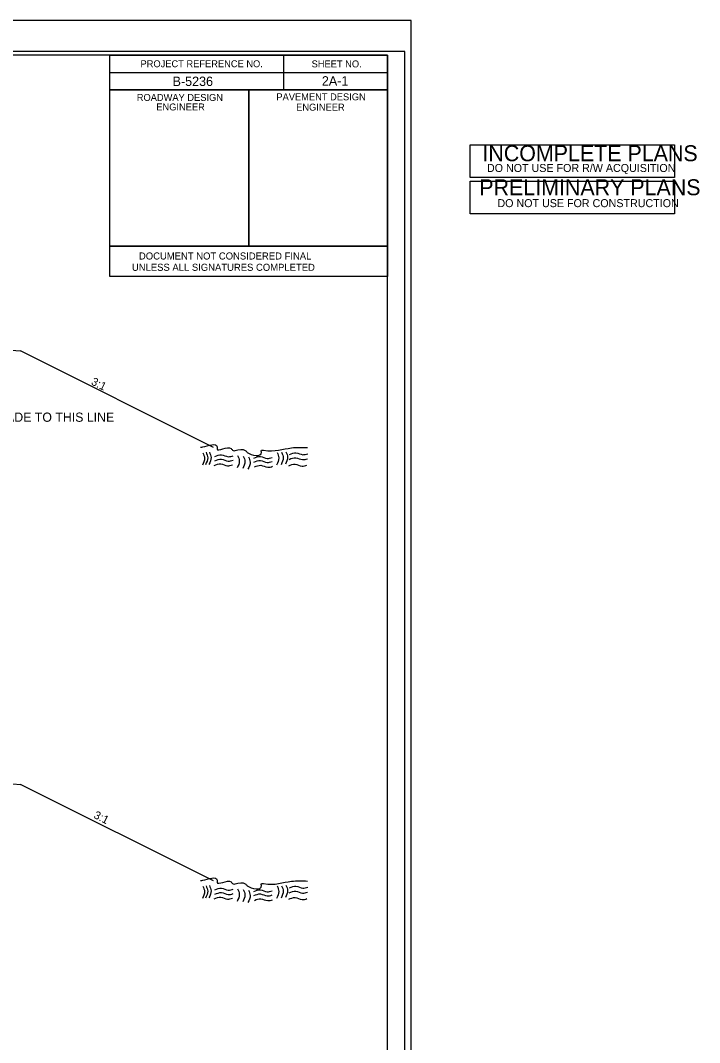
# Model space of a CAD drawing. Extents: x 1733676 to 1734289, y 540979 to 541226.
# Drawn here: x 1734236.1 to 1734288.9, y 541146.4 to 541225.9 of the extents above; entities that cross this region are included whole.
import ezdxf

# ---------------------------------------------------------------- set-up
doc = ezdxf.new("R2010")
doc.units = 0
for name, color, linetype in [('Old_Level_2', 7, 'Continuous'), ('Sheet Cutting Line CELL', 7, 'Continuous'), ('Sheet Data Field CELL', 7, 'Continuous'), ('Sheet Plot Border Inside CELL', 7, 'Continuous'), ('Sheet Plot Border Outside CELL', 7, 'Continuous'), ('Sheet Sticker Exception Certification CELL', 7, 'Continuous'), ('Sheet Sticker Incomplete CELL', 7, 'Continuous'), ('Sheet Sticker Preliminary CELL', 7, 'Continuous'), ('Sheet Typical CELL', 7, 'Continuous'), ('Typical Pavement Slope CELL', 7, 'Continuous'), ('Typical Slope Point Local CELL', 7, 'Continuous'), ('Typical Text General CELL', 7, 'Continuous')]:
    doc.layers.add(name, color=color, linetype=linetype)

msp = doc.modelspace()

# ---------------------------------------------------------------- linework, layer by layer
at = {"layer": 'Old_Level_2'}
for points in [[(1734250.132, 541192.695), (1734250.318, 541192.717), (1734251.415, 541192.73), (1734251.417, 541192.573), (1734252.513, 541192.586), (1734252.671, 541192.431), (1734252.828, 541192.433), (1734253.611, 541192.442), (1734253.77, 541192.287), (1734254.866, 541192.3), (1734254.864, 541192.456), (1734255.021, 541192.458), (1734257.212, 541192.64), (1734258.46, 541192.655)], [(1734250.315, 541192.256), (1734250.443, 541191.836), (1734250.274, 541191.29)], [(1734250.56, 541192.294), (1734250.688, 541191.874), (1734250.519, 541191.328)], [(1734250.823, 541192.314), (1734250.951, 541191.895), (1734250.782, 541191.349)], [(1734251.257, 541191.977), (1734251.764, 541192.106), (1734252.292, 541191.954), (1734252.677, 541192.029)], [(1734253.019, 541192.042), (1734253.147, 541191.622), (1734252.978, 541191.076)], [(1734253.459, 541191.994), (1734253.586, 541191.574), (1734253.417, 541191.028)], [(1734254.276, 541191.837), (1734254.784, 541191.965), (1734255.312, 541191.814), (1734255.697, 541191.888)], [(1734256.087, 541192.27), (1734256.215, 541191.851), (1734256.046, 541191.305)], [(1734256.438, 541192.292), (1734256.565, 541191.872), (1734256.396, 541191.326)], [(1734256.771, 541192.331), (1734256.898, 541191.911), (1734256.729, 541191.365)], [(1734257.045, 541192.132), (1734257.552, 541192.261), (1734258.08, 541192.109), (1734258.466, 541192.184)], [(1734251.195, 541191.275), (1734251.702, 541191.403), (1734252.23, 541191.252), (1734252.615, 541191.326)], [(1734251.243, 541191.626), (1734251.751, 541191.755), (1734252.279, 541191.603), (1734252.664, 541191.678)], [(1734253.863, 541191.946), (1734253.99, 541191.527), (1734253.821, 541190.981)], [(1734254.28, 541191.521), (1734254.787, 541191.65), (1734255.315, 541191.498), (1734255.7, 541191.573)], [(1734254.319, 541191.153), (1734254.827, 541191.282), (1734255.355, 541191.13), (1734255.74, 541191.204)], [(1734256.985, 541191.237), (1734257.493, 541191.365), (1734258.021, 541191.213), (1734258.406, 541191.288)], [(1734257.032, 541191.746), (1734257.539, 541191.874), (1734258.067, 541191.723), (1734258.452, 541191.797)], [(1734250.132, 541158.995), (1734250.318, 541159.018), (1734251.415, 541159.03), (1734251.417, 541158.874), (1734252.513, 541158.887), (1734252.671, 541158.732), (1734252.828, 541158.734), (1734253.611, 541158.743), (1734253.77, 541158.588), (1734254.866, 541158.6), (1734254.864, 541158.757), (1734255.021, 541158.759), (1734257.212, 541158.941), (1734258.46, 541158.955)], [(1734250.56, 541158.594), (1734250.688, 541158.175), (1734250.519, 541157.629)], [(1734250.823, 541158.615), (1734250.951, 541158.195), (1734250.782, 541157.649)], [(1734256.771, 541158.631), (1734256.898, 541158.212), (1734256.729, 541157.666)], [(1734250.315, 541158.557), (1734250.443, 541158.137), (1734250.274, 541157.591)], [(1734251.243, 541157.927), (1734251.751, 541158.055), (1734252.279, 541157.904), (1734252.664, 541157.978)], [(1734251.257, 541158.278), (1734251.764, 541158.407), (1734252.292, 541158.255), (1734252.677, 541158.329)], [(1734253.019, 541158.342), (1734253.147, 541157.923), (1734252.978, 541157.377)], [(1734253.459, 541158.295), (1734253.586, 541157.875), (1734253.417, 541157.329)], [(1734253.863, 541158.247), (1734253.99, 541157.827), (1734253.821, 541157.281)], [(1734254.276, 541158.137), (1734254.784, 541158.266), (1734255.312, 541158.114), (1734255.697, 541158.189)], [(1734254.28, 541157.822), (1734254.787, 541157.95), (1734255.315, 541157.798), (1734255.7, 541157.873)], [(1734256.087, 541158.571), (1734256.215, 541158.151), (1734256.046, 541157.605)], [(1734256.438, 541158.592), (1734256.565, 541158.173), (1734256.396, 541157.627)], [(1734257.032, 541158.046), (1734257.539, 541158.175), (1734258.067, 541158.023), (1734258.452, 541158.098)], [(1734257.045, 541158.433), (1734257.552, 541158.561), (1734258.08, 541158.41), (1734258.466, 541158.484)], [(1734251.195, 541157.575), (1734251.702, 541157.704), (1734252.23, 541157.552), (1734252.615, 541157.627)], [(1734254.319, 541157.454), (1734254.827, 541157.582), (1734255.355, 541157.431), (1734255.74, 541157.505)], [(1734256.985, 541157.537), (1734257.493, 541157.666), (1734258.021, 541157.514), (1734258.406, 541157.589)]]:
    msp.add_spline(points, degree=3, dxfattribs=at)
at = {"layer": 'Sheet Cutting Line CELL'}
msp.add_line((1734266.513, 541225.875), (1734084.641, 541225.875), dxfattribs=at)
at = {"layer": 'Sheet Plot Border Inside CELL'}
msp.add_lwpolyline([(1734266.027, 541223.451), (1734086.045, 541223.451), (1734086.045, 541109.5), (1734266.027, 541109.5)], close=True, dxfattribs=at)
at = {"layer": 'Sheet Plot Border Outside CELL'}
msp.add_lwpolyline([(1734266.513, 541225.875), (1734084.641, 541225.875), (1734084.641, 541107.075), (1734266.513, 541107.075)], close=True, dxfattribs=at)
at = {"layer": 'Sheet Sticker Exception Certification CELL'}
for p, q in [((1734243.071, 541205.97), (1734243.071, 541208.32)), ((1734243.071, 541208.32), (1734264.677, 541208.32)), ((1734264.677, 541208.319), (1734264.677, 541205.969)), ((1734264.677, 541205.97), (1734243.071, 541205.97))]:
    msp.add_line(p, q, dxfattribs=at)
at = {"layer": 'Sheet Sticker Incomplete CELL'}
msp.add_lwpolyline([(1734271.092, 541213.664), (1734271.092, 541216.202), (1734286.968, 541216.202), (1734286.968, 541213.664)], close=True, dxfattribs=at)
at = {"layer": 'Sheet Sticker Preliminary CELL'}
msp.add_lwpolyline([(1734271.092, 541210.844), (1734271.092, 541213.382), (1734286.968, 541213.382), (1734286.968, 541210.844)], close=True, dxfattribs=at)
at = {"layer": 'Sheet Typical CELL'}
for p, q in [((1734256.577, 541223.17), (1734256.577, 541220.47)), ((1734243.071, 541221.82), (1734264.677, 541221.82)), ((1734253.877, 541220.47), (1734253.877, 541208.325))]:
    msp.add_line(p, q, dxfattribs=at)
for points in [[(1734264.677, 541223.175), (1734102.677, 541223.175), (1734102.677, 541109.775), (1734264.677, 541109.775)], [(1734243.071, 541223.175), (1734264.677, 541223.175), (1734264.677, 541220.47), (1734243.071, 541220.47)], [(1734243.071, 541220.47), (1734253.877, 541220.47), (1734253.877, 541208.32), (1734243.071, 541208.32)], [(1734253.877, 541220.47), (1734264.677, 541220.47), (1734264.677, 541208.32), (1734253.877, 541208.32)]]:
    msp.add_lwpolyline(points, close=True, dxfattribs=at)
at = {"layer": 'Typical Pavement Slope CELL'}
for p, q in [((1734234.135, 541200.34), (1734236.135, 541200.173)), ((1734234.139, 541166.641), (1734236.14, 541166.474))]:
    msp.add_line(p, q, dxfattribs=at)
at = {"layer": 'Typical Slope Point Local CELL'}
for p, q in [((1734251.133, 541192.674), (1734236.135, 541200.173)), ((1734251.137, 541158.975), (1734236.14, 541166.474))]:
    msp.add_line(p, q, dxfattribs=at)

# ---------------------------------------------------------------- texts
at = {"layer": 'Sheet Data Field CELL'}
for s, p in [('B-5236', (1734247.961, 541220.778)), ('2A-1', (1734259.566, 541220.81))]:
    msp.add_text(s, height=0.729, dxfattribs=at).set_placement(p)
at = {"layer": 'Sheet Sticker Exception Certification CELL'}
for s, p in [('DOCUMENT NOT CONSIDERED FINAL', (1734245.347, 541207.285)), ('UNLESS ALL SIGNATURES COMPLETED', (1734244.799, 541206.405))]:
    msp.add_text(s, height=0.55, dxfattribs=at).set_placement(p)
at = {"layer": 'Sheet Sticker Incomplete CELL'}
for s, height, p in [('INCOMPLETE PLANS', 1.24416, (1734272.043, 541214.927)), ('DO NOT USE FOR R/W ACQUISITION', 0.62208, (1734272.399, 541214.093))]:
    msp.add_text(s, height=height, dxfattribs=at).set_placement(p)
at = {"layer": 'Sheet Sticker Preliminary CELL'}
for s, height, p in [('PRELIMINARY PLANS', 1.24416, (1734271.802, 541212.281)), ('DO NOT USE FOR CONSTRUCTION', 0.62208, (1734273.212, 541211.357))]:
    msp.add_text(s, height=height, dxfattribs=at).set_placement(p)
at = {"layer": 'Sheet Typical CELL'}
for s, height, p in [('PROJECT REFERENCE NO.', 0.54001, (1734245.469, 541222.236)), ('SHEET NO.', 0.54, (1734258.769, 541222.225)), ('ROADWAY DESIGN', 0.54001, (1734245.177, 541219.617)), ('PAVEMENT DESIGN', 0.54001, (1734256.031, 541219.665)), ('ENGINEER', 0.54, (1734246.695, 541218.877)), ('ENGINEER', 0.54, (1734257.565, 541218.861))]:
    msp.add_text(s, height=height, dxfattribs=at).set_placement(p)
at = {"layer": 'Typical Slope Point Local CELL'}
for p in [(1734241.578, 541197.593), (1734241.775, 541163.886)]:
    msp.add_text('3:1', height=0.6249, rotation=333.43495, dxfattribs=at).set_placement(p)
at = {"layer": 'Typical Text General CELL'}
msp.add_text('GRADE TO THIS LINE', height=0.71614, dxfattribs=at).set_placement((1734233.581, 541194.667))

doc.saveas('drawing.dxf')
